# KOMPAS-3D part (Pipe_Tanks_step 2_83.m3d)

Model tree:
1. X Axis
2. Y Axis
3. Z Axis  (labels: Bend 90 Dn 50; Pipe Dn 50)
     Òîëùèíà ñòåíêè 1 = 1

Referenced files in C:\Documents and Settings\kashirsky\Мои документы\Camtasia Studio\Pipelines3D\Tanks\: Tanks_step 2.a3d
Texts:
  Pipe Dn 50
  Steel ASTM A295
  Three Point Plane
  Plane at Angle
  Line and Point Plane
  Axis through Two Vertices
  Axis of Feature
  Axis of Conical Surface
  Axis through Edge
  Trim by Surface
  Trim by Sketch
  Feature with No History
  Intersection Axis of Two Planes
  Two Line Plane
  Line and Face Plane
  Bend by line
  Hole in sheet body
  Cut in sheet body
  Point in CM
  Linear Dimension from Line to Point
  Surface Finish Symbol
  Geometric Tolerance Symbol
  Leader #1
  Leader #2
  Leader #3
  Shape Deviations and Datum
  Node point number
  Mark of coordination axis
  Node point designation
  Mark/Reference designation with leader
  Mark/reference designation on line
  Mark/Reference designation without leader
  Bend 90 Dn 50
  Plane of section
